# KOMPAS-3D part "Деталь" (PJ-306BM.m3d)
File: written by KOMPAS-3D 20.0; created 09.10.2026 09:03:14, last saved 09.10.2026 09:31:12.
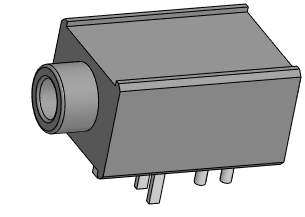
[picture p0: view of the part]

Document properties: Полное имя файла: D:\Install\kompas\kompas\KOMPAS-3D v20\Work\PJ-306BM.m3d

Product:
- Part/product: Деталь
    Масса: 0.0149267
  - Body: Тело 1
      Масса: 0.0147247

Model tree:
1. Эскиз:1
2. Элемент выдавливания:1
     Расстояние 1 = 17.5
3. Фаска:1  (with: Элемент выдавливания:1)
     Угол = 45; Длина 1 = 0.5; Длина 2 = 0.5
4. Эскиз:2  (with: Элемент выдавливания:1)
5. Элемент выдавливания:2
     Расстояние 2 = 17.5
6. Эскиз:3  (with: Элемент выдавливания:1)
7. Элемент выдавливания:3
     Расстояние 1 = 3.5
8. Скругление:1  (with: Элемент выдавливания:3, Элемент выдавливания:1)
     Радиус = 0.25
9. Эскиз:4  (with: Элемент выдавливания:2, Фаска:1)
10. Элемент выдавливания:4
     Расстояние 1 = 3.6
